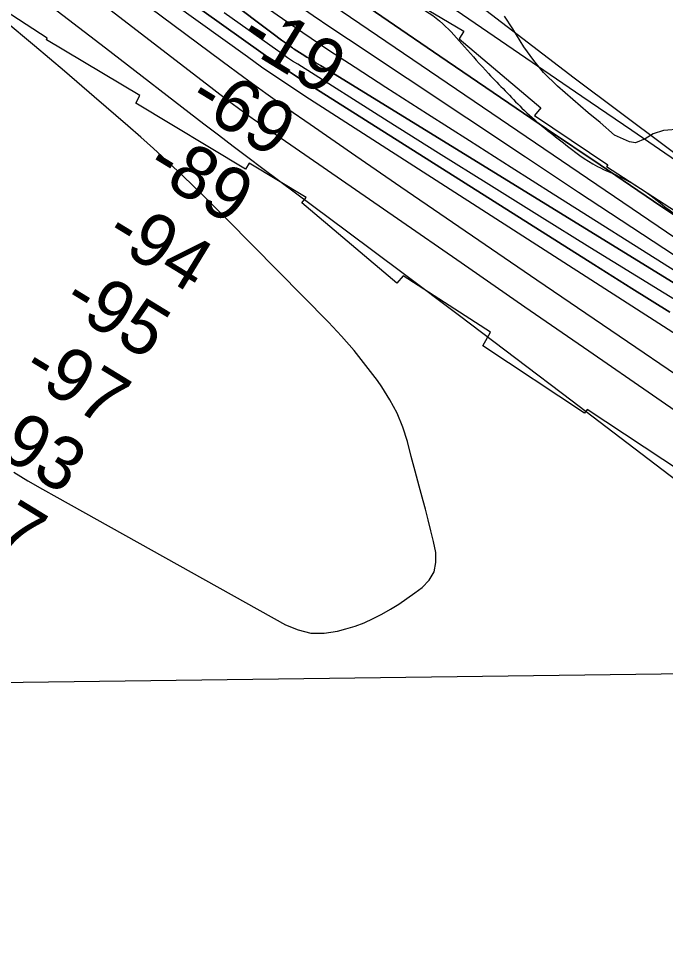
# Model space of a CAD drawing. Extents: x 3734862 to 3772949, y 391520 to 417239.
# Drawn here: x 3764747 to 3765564, y 396853 to 398025 of the extents above; entities that cross this region are included whole.
import ezdxf

# ---------------------------------------------------------------- set-up
doc = ezdxf.new("R2010")
doc.units = 0
for name, color, linetype in [('V-GRID-FRAM', 7, 'Continuous'), ('V-RIVR-EDGE', 7, 'Continuous'), ('V-RIVR-RANG', 7, 'Continuous'), ('V-RRAP-FSHR', 7, 'Continuous'), ('V-RRAP-RVMT', 7, 'Continuous'), ('V-SITE-VEGE', 7, 'Continuous'), ('V-TOPO-DPTH', 7, 'Continuous'), ('V-TOPO-MAJR', 7, 'Continuous'), ('V-TOPO-MINR', 7, 'Continuous'), ('V-TOPO-WATR', 7, 'Continuous')]:
    doc.layers.add(name, color=color, linetype=linetype)

msp = doc.modelspace()

# ---------------------------------------------------------------- linework, layer by layer
at = {"layer": 'V-GRID-FRAM'}
msp.add_lwpolyline([(3738832.3, 415033.8), (3770599.2, 415447.4), (3770843.8, 397266.6), (3739061.1, 396852.8), (3738832.3, 415033.8)], dxfattribs=at)
at = {"layer": 'V-RIVR-EDGE'}
msp.add_spline([(3755702.1, 404495.3), (3755757.2, 404470.8), (3755793.3, 404451.2), (3755852.5, 404424.4), (3755881.4, 404415.7), (3755906.2, 404404.4), (3755920.2, 404395.8), (3755948.7, 404379.4), (3755958.2, 404378.9), (3755969, 404378), (3755990.7, 404368.5), (3756022.8, 404350.3), (3756054.8, 404336.6), (3756079.7, 404323), (3756103.6, 404309.4), (3756144.2, 404288), (3756167.7, 404269), (3756188.9, 404253.6), (3756231.4, 404233.1), (3756271.6, 404217.2), (3756299.1, 404203.1), (3756403, 404163.5), (3756460.4, 404140.3), (3756508.7, 404114.9), (3756530.8, 404104), (3756588.2, 404078), (3756639.2, 404052.1), (3756694.3, 404019.5), (3756726.8, 403998.1), (3756735.8, 403989.1), (3756740.3, 403979.6), (3756740.3, 403973.2), (3756740.7, 403967.8), (3756747.5, 403960.5), (3756759.7, 403953.7), (3756786.3, 403941.5), (3756814.3, 403929.2), (3756864.5, 403904.6), (3756889.3, 403896), (3756899.7, 403897.3), (3756908.3, 403901.8), (3756919.2, 403901.3), (3756933.2, 403894.1), (3756945.8, 403892.7), (3756956.2, 403893.1), (3756962.1, 403897.2), (3756970.7, 403896.7), (3756978.4, 403894.4), (3756992.4, 403894.8), (3757002.8, 403897.5), (3757019.1, 403901.5), (3757027.7, 403901.5), (3757034, 403901.1), (3757036.3, 403896.5), (3757036.7, 403891.1), (3757038.5, 403883.4), (3757046.6, 403874.3), (3757060.6, 403866.2), (3757076.4, 403853.9), (3757104.4, 403831.2), (3757122.4, 403816.7), (3757145.5, 403804.5), (3757165.3, 403796.7), (3757181.6, 403787.2), (3757194.2, 403777.7), (3757213.6, 403765.4), (3757229.9, 403756.3), (3757251.6, 403745.9), (3757266.5, 403741.3), (3757283.2, 403734.5), (3757308.9, 403720.9), (3757360.4, 403694.1), (3757393.8, 403670.9), (3757430, 403657.3), (3757461.6, 403645.4), (3757505.4, 403628.1), (3757548.3, 403610.4), (3757591.7, 403587.2), (3757649.5, 403552.3), (3757711.8, 403512.8), (3757753.8, 403493.2), (3757766.9, 403487.8), (3757773.2, 403487.8), (3757785.9, 403494.1), (3757794.5, 403494), (3757803.5, 403489.5), (3757807.1, 403480.9), (3757810.6, 403456), (3757814.2, 403447.9), (3757826.4, 403437), (3757854.4, 403422.9), (3757930.3, 403373.9), (3757975.8, 403342.6), (3758005.2, 403323.5), (3758062.1, 403286.7), (3758092.3, 403263.6), (3758175.8, 403209.6), (3758234.5, 403169.2), (3758283.7, 403133.8), (3758328.8, 403103.4), (3758399.2, 403041.7), (3758421.8, 403023.1), (3758438.1, 403017.7), (3758463.8, 403017.6), (3758491.4, 403026.1), (3758504.5, 403022), (3758513.6, 403014.3), (3758514, 403006.2), (3758499.9, 402997.2), (3758498.1, 402989.9), (3758502.2, 402978.2), (3758510.7, 402969.6), (3758522, 402962.8), (3758545, 402948.7), (3758582.1, 402926.9), (3758650.2, 402878.8), (3758697.6, 402840.7), (3758721.5, 402820.3), (3758740.9, 402809.4), (3758782, 402784.9), (3758831.2, 402755.4), (3758902.1, 402711.8), (3758960.4, 402675.5), (3759018.6, 402634.6), (3759069.6, 402599.7), (3759134.6, 402553.4), (3759185.6, 402508.1), (3759223.5, 402478.1), (3759262.3, 402448.2), (3759321.4, 402402.4), (3759371.5, 402366.1), (3759431.5, 402323.4), (3759463.6, 402300.3), (3759488.9, 402281.7), (3759576.9, 402222.7), (3759627, 402186.8), (3759672.1, 402153.7), (3759778.2, 402087.4), (3759832.8, 402050.7), (3759873, 402019.4), (3759909.5, 401989.4), (3760050.8, 401883.7), (3760100, 401850.2), (3760145.6, 401819.3), (3760185.8, 401788), (3760211.9, 401766.7), (3760254.8, 401734.5), (3760285.5, 401709.1), (3760303.1, 401700.5), (3760325.3, 401691.4), (3760352.8, 401671.4), (3760391.1, 401641), (3760430.4, 401612), (3760461.6, 401590.2), (3760536.9, 401543), (3760583, 401510.8), (3760602.8, 401495.8), (3760629, 401477.2), (3760672.4, 401449.5), (3760711.2, 401426.8), (3760818.6, 401347.8), (3760872.3, 401310.6), (3760925.6, 401271.6), (3760948.6, 401251.7), (3761039.8, 401181.8), (3761107, 401135.5), (3761151.7, 401104.7), (3761172.9, 401093.3), (3761186, 401090.6), (3761199.2, 401092.8), (3761219.5, 401099.1), (3761228.1, 401099.5), (3761233.5, 401095.4), (3761236.7, 401087.7), (3761236.6, 401077.8), (3761228.5, 401063.8), (3761223, 401057.5), (3761223, 401049.3), (3761228.9, 401039.4), (3761242.4, 401026.7), (3761254.1, 401021.7), (3761266.8, 401018.5), (3761292.5, 401001.7), (3761317.3, 400980.4), (3761342.1, 400955.4), (3761463.1, 400853.4), (3761510, 400812.1), (3761550.2, 400777.7), (3761585.3, 400746.8), (3761681.5, 400674.3), (3761756.4, 400618.9), (3761817.8, 400572.2), (3761878.3, 400530.4), (3761996.5, 400436.5), (3762057.4, 400389.8), (3762104.8, 400352.6), (3762156.3, 400313.2), (3762204.5, 400277.3), (3762245.2, 400247.8), (3762291.6, 400210.2), (3762325.9, 400182.1), (3762356.2, 400159.8), (3762404, 400123.6), (3762432.9, 400101.3), (3762455.5, 400091.3), (3762473.5, 400075.9), (3762512.3, 400044.2), (3762551.6, 400012.4), (3762593.6, 399983.8), (3762620.2, 399963.4), (3762661.7, 399937.1), (3762686.6, 399919.8), (3762793.1, 399841.3), (3762834.6, 399812.8), (3762873.4, 399790.1), (3762923.1, 399758.3), (3762957, 399737.4), (3762984, 399721.5), (3763024.2, 399693.4), (3763075.2, 399657.5), (3763115.9, 399633.9), (3763172.8, 399601.2), (3763228.7, 399568.5), (3763285.2, 399533.6), (3763344.3, 399494.1), (3763398.5, 399455.1), (3763444.1, 399421), (3763484.7, 399391.1), (3763603.4, 399303.1), (3763654.8, 399261.8), (3763661.1, 399259.5), (3763667, 399254.5), (3763672, 399245), (3763696.3, 399224.2), (3763722.9, 399200.1), (3763745.5, 399180.2), (3763818.1, 399117.2), (3763841.6, 399099.5), (3763852.4, 399092.2), (3763858.8, 399084.1), (3763875, 399067.3), (3763898, 399046), (3763924.6, 399023.8), (3763949, 399007.9), (3763970.2, 398987.5), (3764004, 398952.6), (3764028.4, 398926.7), (3764056.8, 398899.5), (3764092.9, 398862.4), (3764130.8, 398826.1), (3764147, 398811.6), (3764152.9, 398799.8), (3764162.3, 398783.5), (3764173.6, 398768.6), (3764186.7, 398757.2), (3764206.1, 398746.3), (3764226.9, 398742.2), (3764246.3, 398733.6), (3764269.3, 398717.7), (3764284.2, 398703.2), (3764301.8, 398691.8), (3764323, 398678.2), (3764345.1, 398661), (3764412.4, 398596.6), (3764457, 398559.9), (3764502.6, 398522.7), (3764538.3, 398497.7), (3764566.3, 398486.4), (3764583.9, 398484.5), (3764604.2, 398486.3), (3764616.5, 398486.2), (3764626.4, 398481.7), (3764630.9, 398474.4), (3764636.3, 398461.3), (3764634.9, 398450), (3764631.7, 398441.4), (3764633.1, 398434.7), (3764636.2, 398430.1), (3764643.9, 398425.6), (3764661.1, 398421.5), (3764685.4, 398409.2), (3764715.2, 398382), (3764745.4, 398356.1), (3764793.3, 398328), (3764844.3, 398292.6), (3764885.8, 398258.1), (3764918.8, 398234.5), (3764992.8, 398187.8), (3765058.3, 398144.2), (3765088.1, 398128.3), (3765140.9, 398100.2), (3765168.9, 398079.7), (3765193.7, 398061.6), (3765246.1, 398042), (3765282.2, 398018.4), (3765309.7, 397989.4), (3765340, 397955.4), (3765361.1, 397933.7), (3765382.3, 397911.9), (3765434.7, 397867.9), (3765477.6, 397838.4), (3765508.7, 397823.9), (3765545.3, 397801.2), (3765575.5, 397778), (3765617.5, 397749.9), (3765653.6, 397726.3), (3765681.6, 397710), (3765727.2, 397684.5), (3765762, 397660), (3765771.9, 397659.5), (3765788.2, 397660), (3765793.6, 397658.1), (3765793.6, 397653.6), (3765785.5, 397648.7), (3765785.5, 397645.5), (3765790.9, 397632.8), (3765800.3, 397623.8), (3765814.8, 397612.9), (3765831.9, 397605.6), (3765847.3, 397603.3), (3765858.1, 397598.7), (3765865.8, 397593.3), (3765888.8, 397577), (3765908.7, 397561.5), (3765918.2, 397548.4), (3765919.5, 397542.1), (3765921.3, 397536.2), (3765926.7, 397533.5), (3765933, 397534.4), (3765940.7, 397533.4), (3765944.8, 397530.3), (3765957, 397519.4), (3765987.7, 397499.9), (3766024.7, 397468.1), (3766059.4, 397438.2), (3766085.1, 397413.3), (3766102.7, 397400.1), (3766131.6, 397377.4), (3766172.7, 397350.2), (3766210.6, 397318.9), (3766264.3, 397285.3), (3766306.8, 397260.8), (3766362.7, 397220.8), (3766381.1, 397208.5)], degree=3, dxfattribs=at)
at = {"layer": 'V-RRAP-FSHR'}
msp.add_lwpolyline([(3763828.7, 399148.5), (3764283.8, 398756.8), (3764610, 398498.2), (3765272, 398085.7), (3765448.1, 397950), (3765966.3, 397562.9), (3766316.1, 397304), (3766451, 397209.4)], dxfattribs=at)
at = {"layer": 'V-RRAP-RVMT'}
for p, q in [((3764782.7, 398000.2), (3764647.6, 398087.5)), ((3765172.5, 398090.1), (3765308.7, 398009)), ((3765308.7, 398009), (3765303, 397999.4)), ((3764781.8, 397998.1), (3764782.7, 398000.2)), ((3764899.9, 397927.6), (3764781.8, 397998.1)), ((3765303, 397999.4), (3765406.3, 397912.2)), ((3764894.8, 397918.2), (3764899.9, 397927.6)), ((3765033.2, 397834.8), (3764894.8, 397918.2)), ((3765406.3, 397912.2), (3765398, 397902.4)), ((3765398, 397902.4), (3765490.6, 397840.1)), ((3765038, 397842.4), (3765033.2, 397834.8)), ((3765109.9, 397798.9), (3765038, 397842.4)), ((3765490.6, 397840.1), (3765489.2, 397838.3)), ((3765489.2, 397838.3), (3765617.6, 397755.1)), ((3765104.5, 397792.3), (3765109.9, 397798.9)), ((3765224.3, 397690.8), (3765104.5, 397792.3)), ((3765232.3, 397700.2), (3765224.3, 397690.8)), ((3765342.7, 397629.3), (3765232.3, 397700.2)), ((3765333, 397612.1), (3765342.7, 397629.3)), ((3765461.4, 397526.9), (3765333, 397612.1)), ((3765464.7, 397531.6), (3765461.4, 397526.9)), ((3765583.9, 397453.1), (3765464.7, 397531.6))]:
    msp.add_line(p, q, dxfattribs=at)
at = {"layer": 'V-SITE-VEGE'}
msp.add_lwpolyline([(3765582.5, 397885.5), (3765561.1, 397883.7), (3765548, 397879.5), (3765537.9, 397873), (3765525.5, 397868.2), (3765518.3, 397869.4), (3765499.3, 397877.7), (3765480.9, 397893.7), (3765466, 397906.1), (3765446.4, 397922.8), (3765427.4, 397939.4), (3765409.6, 397956.6), (3765397.1, 397972), (3765384.6, 397989.2), (3765370.9, 398011.8), (3765360.2, 398027.8)], dxfattribs=at)
at = {"layer": 'V-TOPO-DPTH'}
msp.add_line((3766223.5, 397206.4), (3762379.2, 397156.4), dxfattribs=at)
for points in [[(3764442, 398475.9), (3765071.5, 398003), (3765075.1, 398000.3), (3765078.8, 397997.6), (3765082.4, 397994.9), (3765086.1, 397992.3), (3765092.4, 397987.8), (3765092.9, 397987.4), (3765093.5, 397987.1), (3765094.1, 397986.7), (3765094.7, 397986.3), (3765104.9, 397979.8), (3765110.6, 397976.2), (3765116.4, 397972.7), (3765122.1, 397969.1), (3765127.9, 397965.6), (3765737.6, 397590.8)], [(3764442, 398475.9), (3765071.5, 398003), (3765075.1, 398000.3), (3765078.8, 397997.6), (3765082.4, 397994.9), (3765086.1, 397992.3), (3765092.4, 397987.8), (3765092.9, 397987.4), (3765093.5, 397987.1), (3765094.1, 397986.7), (3765094.7, 397986.3), (3765104.9, 397979.8), (3765110.6, 397976.2), (3765116.4, 397972.7), (3765122.1, 397969.1), (3765127.9, 397965.6), (3765737.6, 397590.8)], [(3766349.9, 397208.1), (3766278.6, 397256.6), (3765850.7, 397545.3), (3765820.6, 397565.4), (3765790.5, 397585.5), (3765760.3, 397605.3), (3765730, 397625.1), (3765655.7, 397673.3), (3765588.4, 397717.2), (3765521.1, 397761.2), (3765453.9, 397805.5), (3765386.8, 397849.8), (3765163.1, 397998.5), (3765140.9, 398013.3), (3765118.8, 398028.3), (3765096.9, 398043.4), (3765075, 398058.6), (3764529.8, 398441.7)], [(3766349.9, 397208.1), (3766278.6, 397256.6), (3765850.7, 397545.3), (3765820.6, 397565.4), (3765790.5, 397585.5), (3765760.3, 397605.3), (3765730, 397625.1), (3765655.7, 397673.3), (3765588.4, 397717.2), (3765521.1, 397761.2), (3765453.9, 397805.5), (3765386.8, 397849.8), (3765163.1, 397998.5), (3765140.9, 398013.3), (3765118.8, 398028.3), (3765096.9, 398043.4), (3765075, 398058.6), (3764529.8, 398441.7)], [(3764928.5, 398071.1), (3765055.5, 397980.4), (3765067.4, 397972.1), (3765079.3, 397963.9), (3765091.4, 397955.9), (3765103.5, 397948.1), (3765472.9, 397714.6), (3765521, 397684.3), (3765569.1, 397654.2)], [(3764928.5, 398071.1), (3765055.5, 397980.4), (3765067.4, 397972.1), (3765079.3, 397963.9), (3765091.4, 397955.9), (3765103.5, 397948.1), (3765472.9, 397714.6), (3765521, 397684.3), (3765569.1, 397654.2)], [(3765148, 398066.9), (3765278.7, 397977.5), (3765346, 397931.5), (3765413.4, 397885.7), (3765481, 397840.1), (3765548.6, 397794.6), (3765800.3, 397625.8), (3765804.9, 397622.7), (3765809.5, 397619.6), (3765814.1, 397616.4), (3765818.7, 397613.2), (3765851.1, 397590.5), (3765871.8, 397575.9), (3765892.5, 397561.3), (3765913.2, 397546.6), (3765933.9, 397531.9), (3765994.3, 397488.8), (3766045.2, 397452.6), (3766096.3, 397416.5), (3766147.4, 397380.7), (3766198.7, 397344.9), (3766394.9, 397208.7)], [(3766268.8, 397207), (3766212.4, 397247.5), (3766139.6, 397299.2), (3766066.6, 397350.4), (3765993, 397400.8), (3765919.1, 397450.8), (3765796.9, 397532.5), (3765783.8, 397541.2), (3765770.6, 397549.7), (3765757.3, 397558.1), (3765744, 397566.4), (3765468.2, 397736.2), (3765404.3, 397775.7), (3765340.5, 397815.3), (3765276.8, 397855.1), (3765213.3, 397895.1), (3765099.1, 397967.2), (3765092.7, 397971.3), (3765086.4, 397975.5), (3765080.2, 397979.8), (3765073.9, 397984.1), (3765006.3, 398032.3)], [(3766268.8, 397207), (3766212.4, 397247.5), (3766139.6, 397299.2), (3766066.6, 397350.4), (3765993, 397400.8), (3765919.1, 397450.8), (3765796.9, 397532.5), (3765783.8, 397541.2), (3765770.6, 397549.7), (3765757.3, 397558.1), (3765744, 397566.4), (3765468.2, 397736.2), (3765404.3, 397775.7), (3765340.5, 397815.3), (3765276.8, 397855.1), (3765213.3, 397895.1), (3765099.1, 397967.2), (3765092.7, 397971.3), (3765086.4, 397975.5), (3765080.2, 397979.8), (3765073.9, 397984.1), (3765006.3, 398032.3)]]:
    msp.add_lwpolyline(points, dxfattribs=at)
at = {"layer": 'V-TOPO-MAJR'}
msp.add_lwpolyline([(3766164.7, 397205.7), (3766164.2, 397206.1), (3766058.5, 397284.2), (3765796.1, 397479.4), (3765773.1, 397496.2), (3765749.9, 397512.7), (3765726.4, 397528.9), (3765702.7, 397544.7), (3765678.9, 397560.3), (3765655, 397575.9), (3765631.1, 397591.4), (3765607.1, 397606.8), (3765108.2, 397927), (3765089.8, 397939), (3765071.5, 397951.3), (3765053.5, 397963.7), (3765035.5, 397976.4), (3764752.6, 398179.9), (3764693.2, 398222.9)], dxfattribs=at)
at = {"layer": 'V-TOPO-MINR'}
for points in [[(3765737.6, 397590.8), (3765127.9, 397965.6), (3765122.1, 397969.1), (3765116.4, 397972.7), (3765110.6, 397976.2), (3765104.9, 397979.8), (3765094.7, 397986.3), (3765094.1, 397986.7), (3765093.5, 397987.1), (3765092.9, 397987.4), (3765092.4, 397987.8), (3765086.1, 397992.3), (3765082.4, 397994.9), (3765078.8, 397997.6), (3765075.1, 398000.3), (3765071.5, 398003), (3764442, 398475.9)], [(3766349.9, 397208.1), (3766278.6, 397256.6), (3765850.7, 397545.3), (3765820.6, 397565.4), (3765790.5, 397585.5), (3765760.3, 397605.3), (3765730, 397625.1), (3765655.7, 397673.3), (3765588.4, 397717.2), (3765521.1, 397761.2), (3765453.9, 397805.5), (3765386.8, 397849.8), (3765163.1, 397998.5), (3765140.9, 398013.3), (3765118.8, 398028.3), (3765096.9, 398043.4), (3765075, 398058.6), (3764529.8, 398441.7)], [(3765705.5, 397440.5), (3765547.3, 397549.6), (3765466.7, 397605.2), (3765386.1, 397660.8), (3765305.6, 397716.5), (3765225, 397772.1), (3765043, 397897.8), (3765041.5, 397898.9), (3765040, 397899.9), (3765038.5, 397901), (3765037.1, 397902.1), (3765024.3, 397911.5), (3765016.5, 397917.3), (3765008.7, 397923.1), (3765000.9, 397929), (3764993.2, 397934.9), (3764384.9, 398402.7)], [(3766460.8, 397209.5), (3766410.7, 397251.5), (3766331.8, 397314.8), (3766251.1, 397375.7), (3766169.1, 397435), (3765891.3, 397629.8), (3765864, 397649), (3765836.5, 397668), (3765809, 397686.9), (3765781.5, 397705.8), (3765710.4, 397754.3), (3765647.2, 397797.3), (3765584.1, 397840.4), (3765521, 397883.6), (3765458, 397926.7), (3765220.7, 398089.2), (3765198, 398104.7), (3765175.1, 398120), (3765152.2, 398135.2), (3765129.2, 398150.2), (3764731.2, 398408.5)], [(3766370.5, 397208.4), (3765852.8, 397560.8), (3765825.2, 397579.5), (3765797.6, 397598.2), (3765770, 397616.8), (3765742.3, 397635.3), (3765714.6, 397653.9), (3765686.9, 397672.4), (3765659.3, 397691.1), (3765631.7, 397709.8), (3765155.2, 398033.3), (3765143.5, 398041.3), (3765131.7, 398049.3), (3765120.1, 398057.4), (3765108.4, 398065.6), (3764966.7, 398165.1), (3764884.6, 398223.6), (3764803, 398282.9), (3764722.2, 398343.2)], [(3766101.3, 397204.9), (3766085.1, 397216.4), (3766013.6, 397267.5), (3765942, 397318.8), (3765870.6, 397370.1), (3765762.8, 397447.7), (3765745.2, 397460.2), (3765727.6, 397472.6), (3765709.8, 397484.9), (3765692.1, 397497.1), (3765401, 397694.8), (3765343.8, 397733.7), (3765286.6, 397772.8), (3765229.5, 397812), (3765172.4, 397851.3), (3765114.7, 397891.1), (3765086.7, 397910.7), (3765058.8, 397930.5), (3765031.1, 397950.5), (3765003.6, 397970.7), (3764544.5, 398311.9)], [(3766329.4, 397207.8), (3766240.2, 397269), (3766135.7, 397339.7), (3765834.2, 397541.5), (3765809.3, 397558), (3765784.3, 397574.4), (3765759.2, 397590.5), (3765734, 397606.6), (3765421.8, 397803.3), (3765368.8, 397836.8), (3765315.9, 397870.4), (3765263.1, 397904.2), (3765210.4, 397938), (3765171.7, 397963), (3765138.6, 397984.7), (3765105.7, 398006.7), (3765073.1, 398029.3), (3765040.7, 398052.1), (3764815.6, 398213.5), (3764751.5, 398259.7), (3764687.6, 398306.1)], [(3765904.5, 397202.3), (3765869.4, 397226.8), (3765829.3, 397255), (3765789.4, 397283.6), (3765749.8, 397312.5), (3765730.4, 397326.7), (3765700.6, 397348.7), (3765670.9, 397370.8), (3765641.3, 397393), (3765611.8, 397415.4), (3765445.6, 397542), (3765374.6, 397596), (3765303.4, 397649.8), (3765232.1, 397703.3), (3765160.6, 397756.7), (3765054.9, 397835.4), (3765036.2, 397849.4), (3765017.6, 397863.4), (3764999.1, 397877.6), (3764980.6, 397891.7), (3764856.2, 397987.6), (3764775.4, 398049.7), (3764694.6, 398111.7)], [(3765569.1, 397654.2), (3765521, 397684.3), (3765472.9, 397714.6), (3765103.5, 397948.1), (3765091.4, 397955.9), (3765079.3, 397963.9), (3765067.4, 397972.1), (3765055.5, 397980.4), (3764928.5, 398071.1)], [(3766268.8, 397207), (3766212.4, 397247.5), (3766139.6, 397299.2), (3766066.6, 397350.4), (3765993, 397400.8), (3765919.1, 397450.8), (3765796.9, 397532.5), (3765783.8, 397541.2), (3765770.6, 397549.7), (3765757.3, 397558.1), (3765744, 397566.4), (3765468.2, 397736.2), (3765404.3, 397775.7), (3765340.5, 397815.3), (3765276.8, 397855.1), (3765213.3, 397895.1), (3765099.1, 397967.2), (3765092.7, 397971.3), (3765086.4, 397975.5), (3765080.2, 397979.8), (3765073.9, 397984.1), (3765006.3, 398032.3)], [(3764740.4, 397452.5), (3764758.4, 397441.7), (3764776.6, 397431.1), (3764794.8, 397420.8), (3765083.7, 397259.9), (3765099.5, 397253.4), (3765115.7, 397249.4), (3765132.4, 397249.4), (3765149.3, 397251.9), (3765159.8, 397254.7), (3765171.7, 397258.4), (3765183.2, 397262.6), (3765194.5, 397267.7), (3765205.5, 397273.3), (3765216.2, 397279.6), (3765226.7, 397286.1), (3765237, 397293), (3765247.2, 397300.2), (3765256.4, 397307), (3765265.1, 397316.3), (3765271.3, 397326.6), (3765273.6, 397338.4), (3765273.4, 397351.2), (3765270.4, 397364.9), (3765267.4, 397378.6), (3765264, 397392.2), (3765260.5, 397405.8), (3765257.7, 397416.2), (3765252.6, 397434.9), (3765247.6, 397453.7), (3765242.6, 397472.4), (3765237.6, 397491.1), (3765231.7, 397509.4), (3765224.5, 397527.1), (3765215.5, 397543.9), (3765205.2, 397560.2), (3765199.7, 397568), (3765185.3, 397587.3), (3765170.2, 397606.2), (3765154.3, 397624.2), (3765137.8, 397641.8), (3765010.1, 397771.2), (3764994.9, 397786.5), (3764979.6, 397801.7), (3764964.1, 397816.7), (3764948.5, 397831.6), (3764932.8, 397846.4), (3764916.9, 397861), (3764900.8, 397875.3), (3764884.6, 397889.6), (3764842.2, 397926.2), (3764804.5, 397958.4), (3764766.7, 397990.5), (3764728.6, 398022.3)]]:
    msp.add_lwpolyline(points, dxfattribs=at)
at = {"layer": 'V-TOPO-WATR'}
msp.add_lwpolyline([(3766394.9, 397208.7), (3766198.7, 397344.9), (3766147.4, 397380.7), (3766096.3, 397416.5), (3766045.2, 397452.6), (3765994.3, 397488.8), (3765933.9, 397531.9), (3765913.2, 397546.6), (3765892.5, 397561.3), (3765871.8, 397575.9), (3765851.1, 397590.5), (3765818.7, 397613.2), (3765814.1, 397616.4), (3765809.5, 397619.6), (3765804.9, 397622.7), (3765800.3, 397625.8), (3765548.6, 397794.6), (3765481, 397840.1), (3765413.4, 397885.7), (3765346, 397931.5), (3765278.7, 397977.5), (3765148, 398066.9)], dxfattribs=at)

# ---------------------------------------------------------------- texts
at = {"layer": 'V-RIVR-RANG'}
for s, p in [('-19', (3765021.8, 397993.2)), ('-69', (3764957.8, 397915.1)), ('-89', (3764904.6, 397830.4)), ('-94', (3764853.1, 397744.7)), ('-95', (3764799.2, 397660.4)), ('-97', (3764748, 397574.5)), ('-93', (3764693.2, 397490.8)), ('-87', (3764642.4, 397404.7))]:
    msp.add_text(s, height=67, rotation=328.5865, dxfattribs=at).set_placement(p)

doc.saveas('drawing.dxf')
